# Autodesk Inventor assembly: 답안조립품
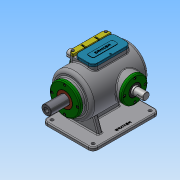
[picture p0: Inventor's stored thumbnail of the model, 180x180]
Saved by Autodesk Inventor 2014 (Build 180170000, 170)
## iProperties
Created: 2018-08
Part Number: 답안조립품
Document SubType Name: Assembly
Designer: net
Mass: 4809.28 g
Surface Area: 4486.65 cm^2
Volume: 2023.67 cm^3
Density: 2.37652 g/cm^3
Author: net
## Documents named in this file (15)
- C:\Users\net\Desktop\380807V1021\380807V1021\답안조립품.iam
- C:\Users\net\Desktop\380807V1021\380807V1021\본체.ipt
- C:\Users\net\Desktop\380807V1021\380807V1021\편심축.ipt
- C:\Users\net\Desktop\380807V1021\380807V1021\베어링 6205.ipt
- 베어링 6205.ipt
- C:\Users\net\Desktop\380807V1021\380807V1021\축 커버.ipt
- C:\Users\net\Desktop\380807V1021\380807V1021\볼트 M4x0.7.ipt
- C:\Users\net\Desktop\380807V1021\380807V1021\오일 실 25 38 8.ipt
- C:\Users\net\Desktop\380807V1021\380807V1021\상부커버.ipt
- C:\Users\net\Desktop\380807V1021\380807V1021\고정플레이트.ipt
- C:\Users\net\Desktop\380807V1021\380807V1021\육각머리볼트 M4.ipt
- C:\Users\net\Desktop\380807V1021\380807V1021\슬라이드.ipt
- C:\Users\net\Desktop\380807V1021\380807V1021\슬라이드 커버.ipt
- C:\Users\net\Desktop\380807V1021\380807V1021\부시.ipt
- C:\Users\net\Desktop\380807V1021\380807V1021\가변스프링.ipt
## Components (14 placed, 3 different names)
1. 고정플레이트:1
2. 가변스프링:1
3. M4x0.7:1
4. M4x0.7:3
5. M4x0.7:4
6. M4x0.7:5
7. M4x0.7:2
8. M4x0.7:6
9. M4x0.7:7
10. M4x0.7:8
11. M4x0.7:9
12. M4x0.7:10
13. M4x0.7:11
14. M4x0.7:12
